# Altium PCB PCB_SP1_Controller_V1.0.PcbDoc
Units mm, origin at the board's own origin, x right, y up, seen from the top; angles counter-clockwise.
Board outline 55.14 x 44.39 mm, 2 copper layers (Top Layer, Bottom Layer); 35 components, 48 nets, 152 pads, 22 vias.
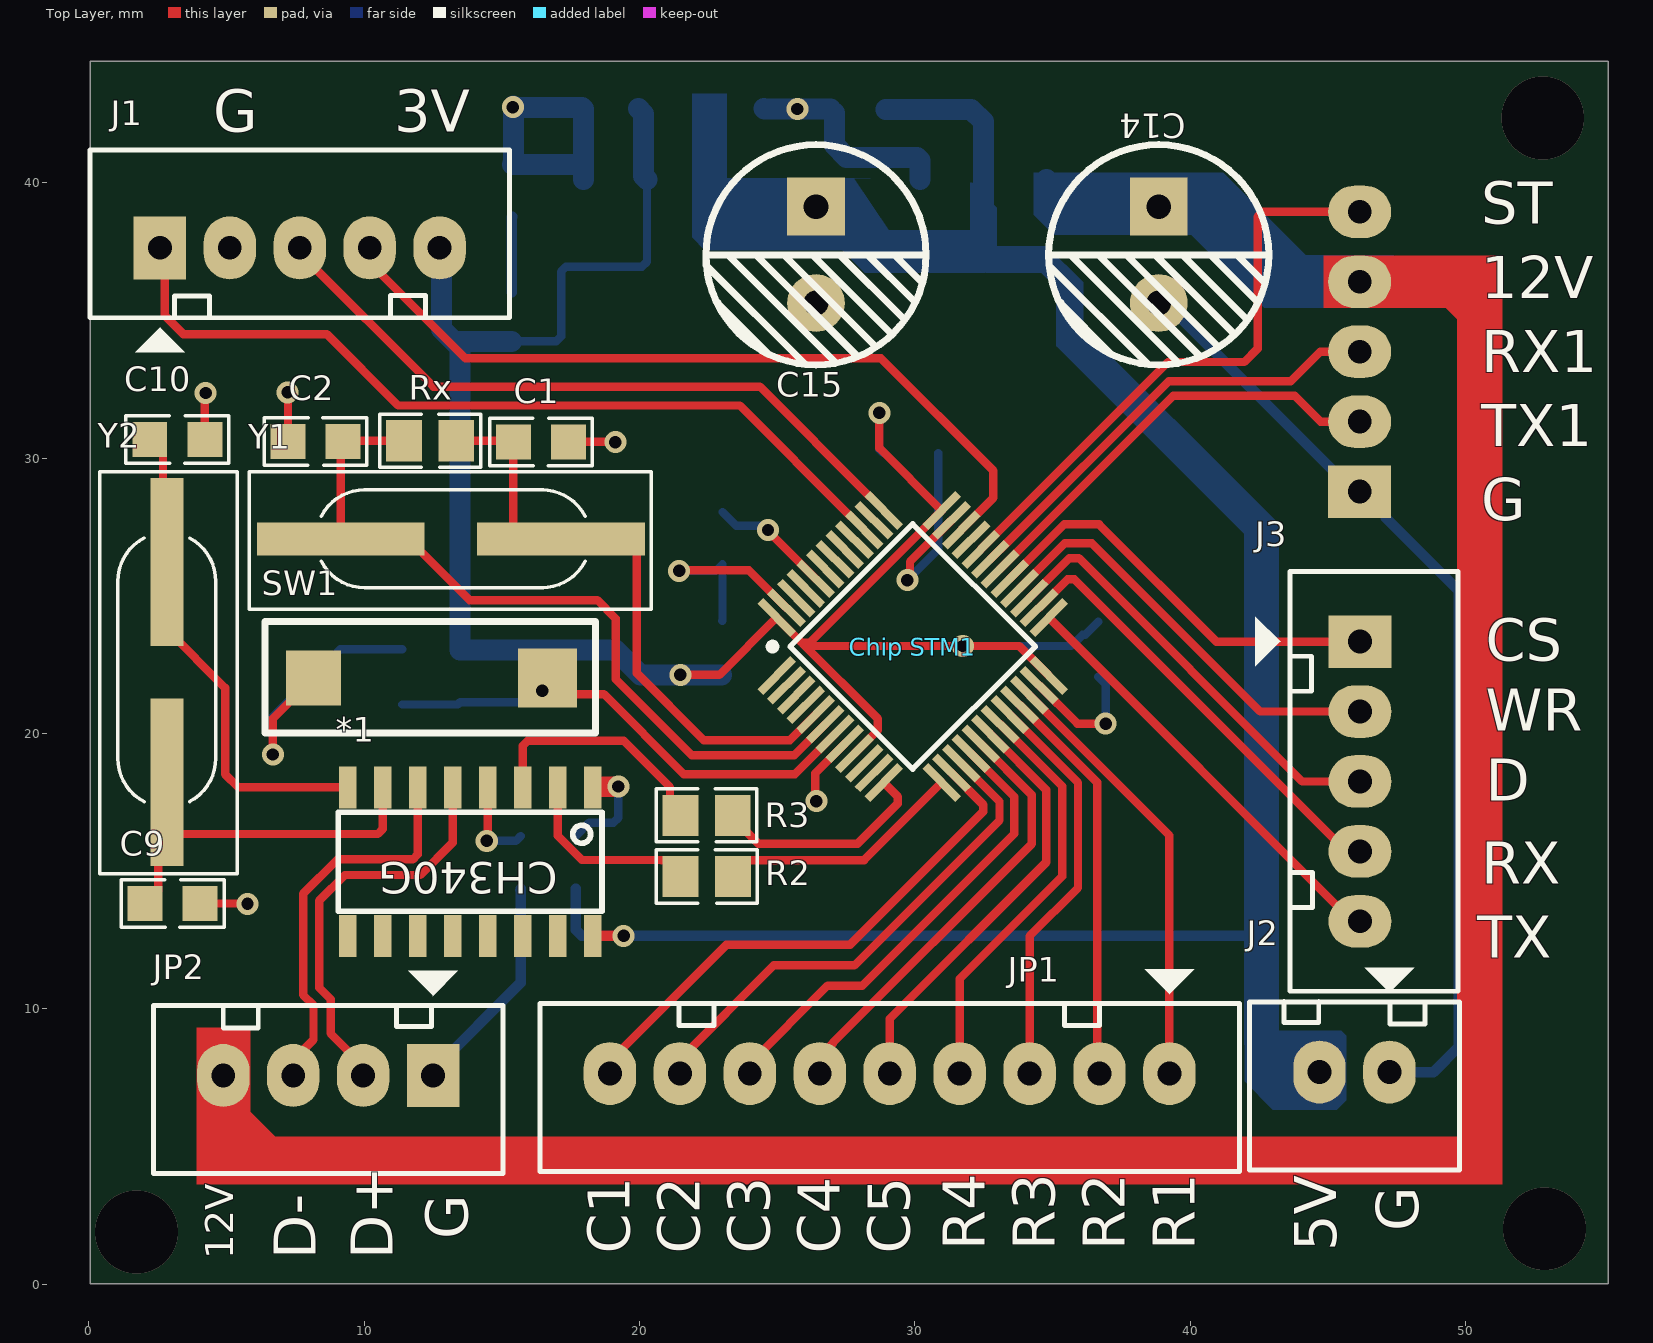
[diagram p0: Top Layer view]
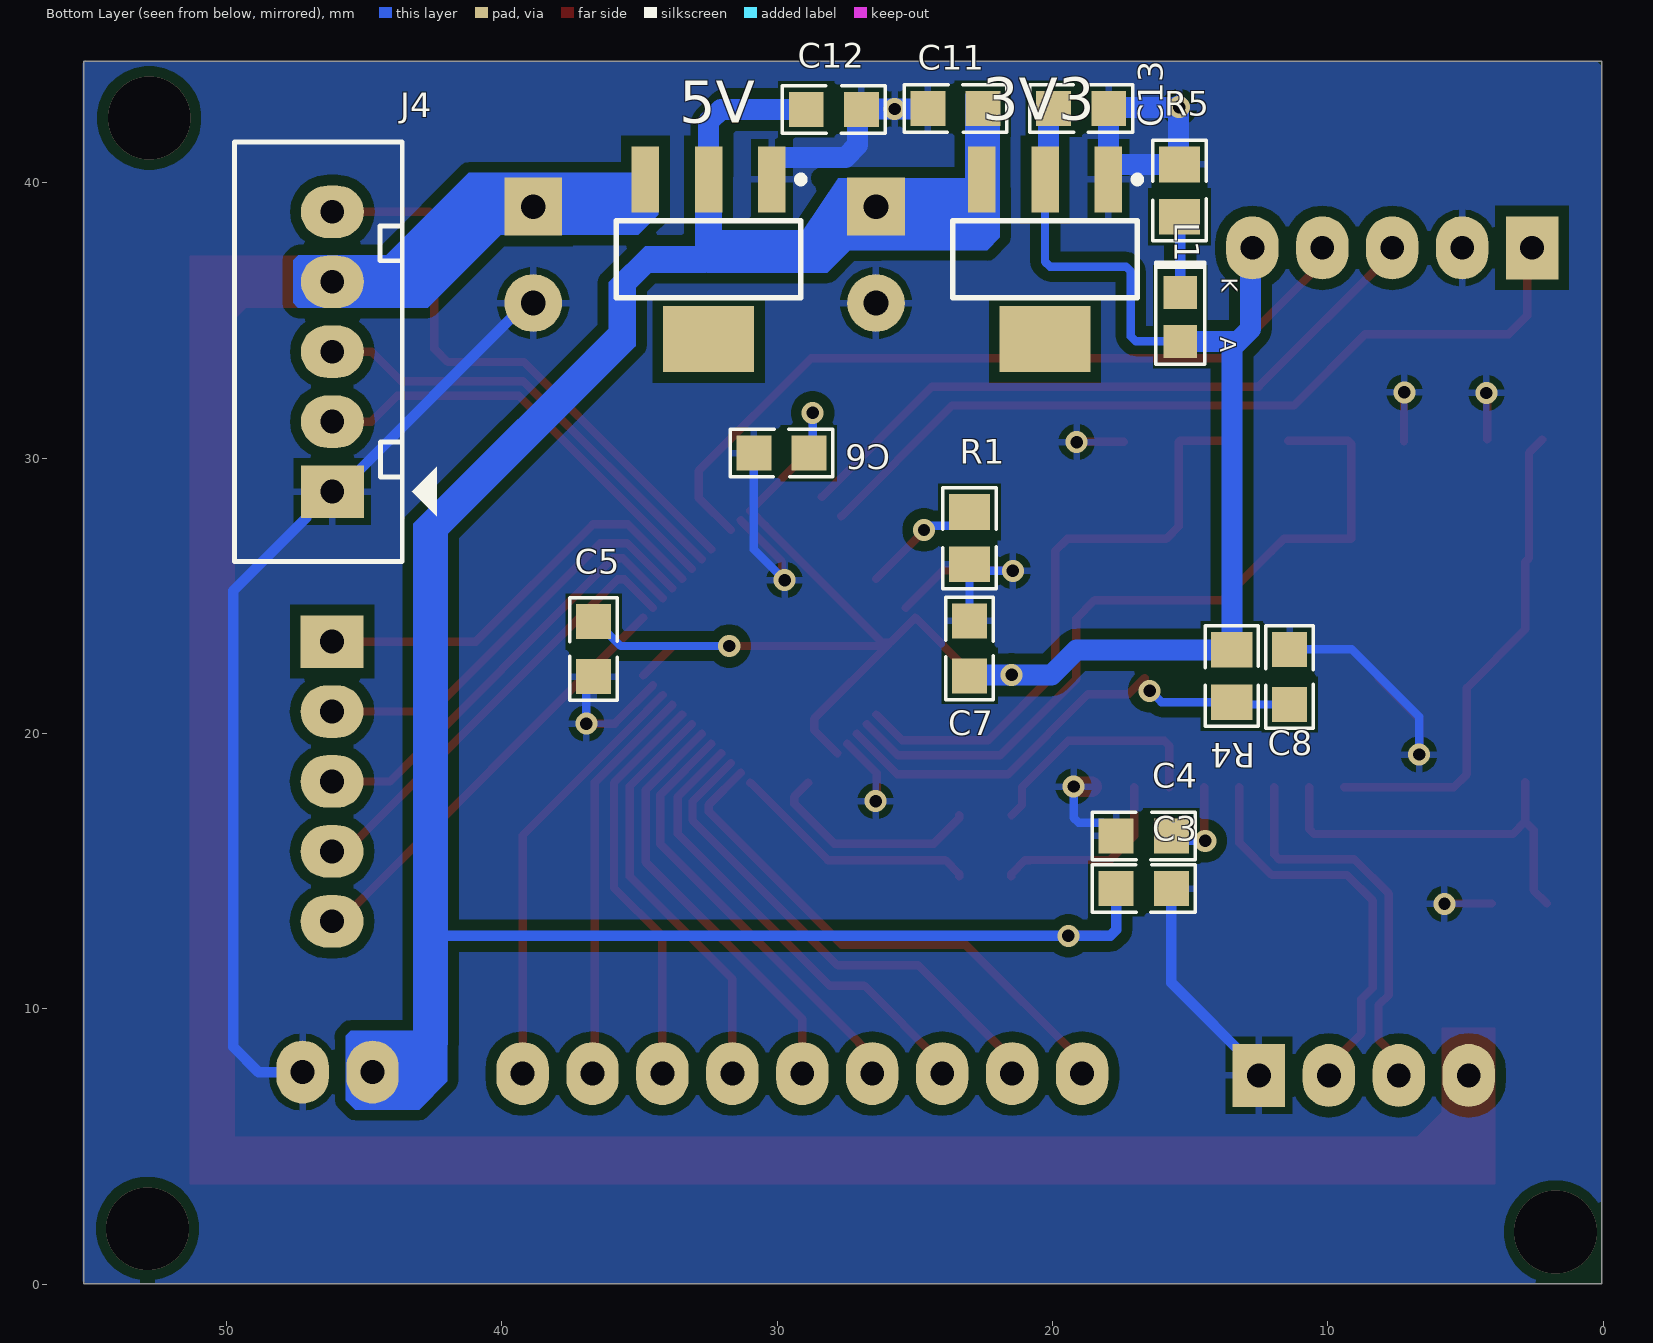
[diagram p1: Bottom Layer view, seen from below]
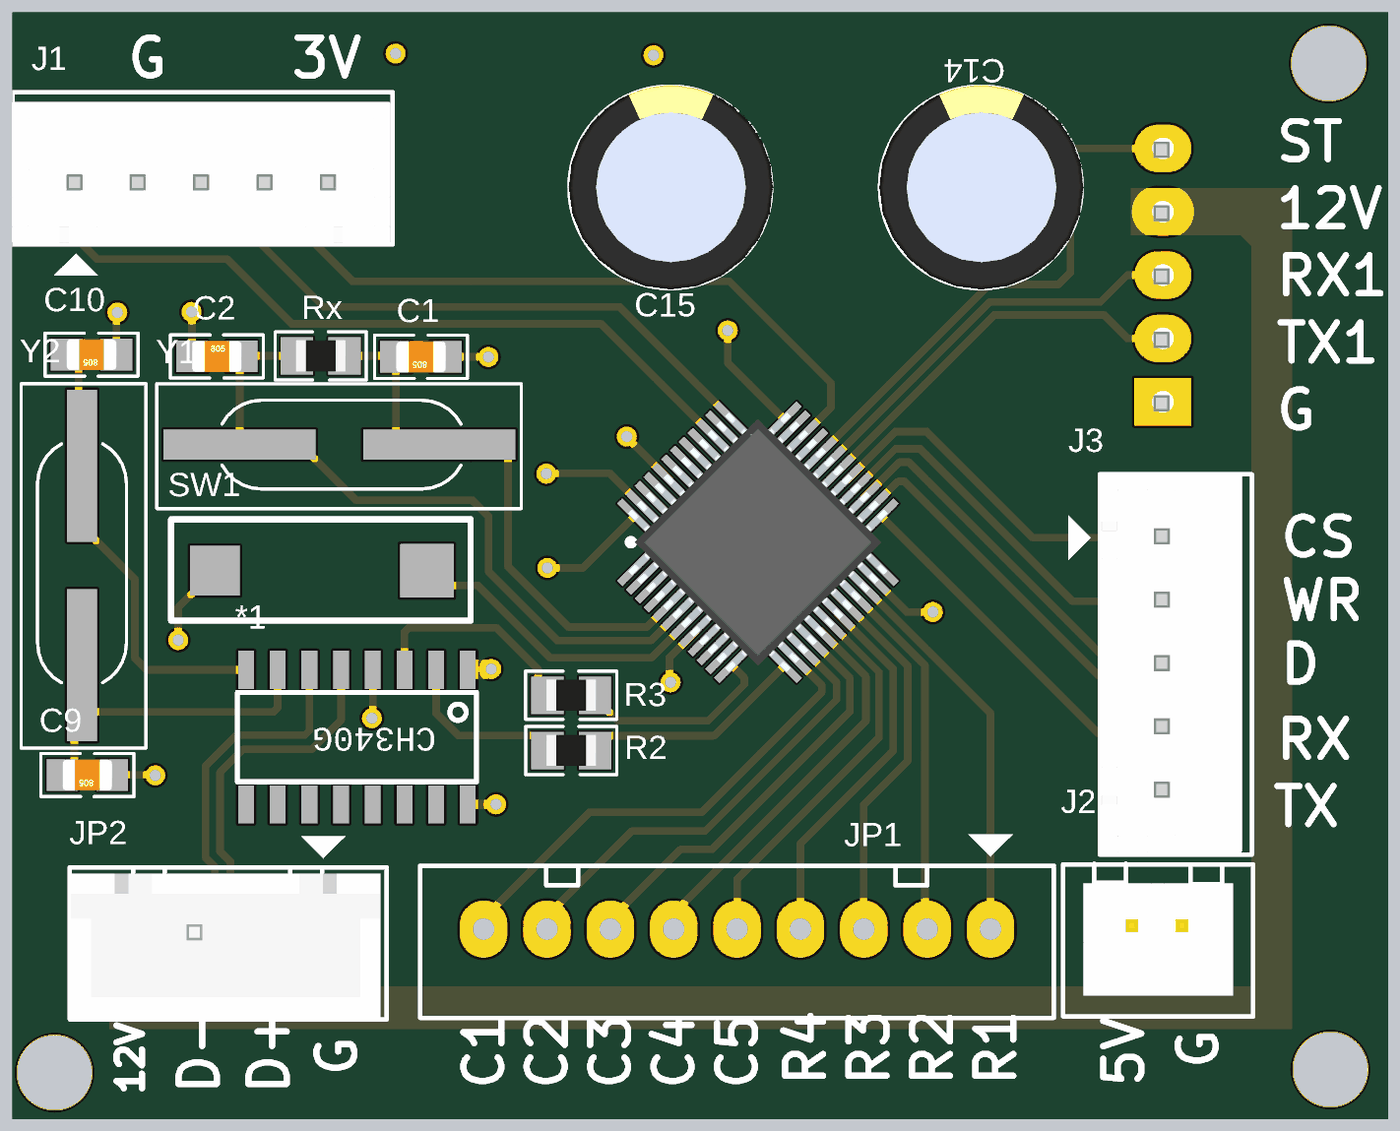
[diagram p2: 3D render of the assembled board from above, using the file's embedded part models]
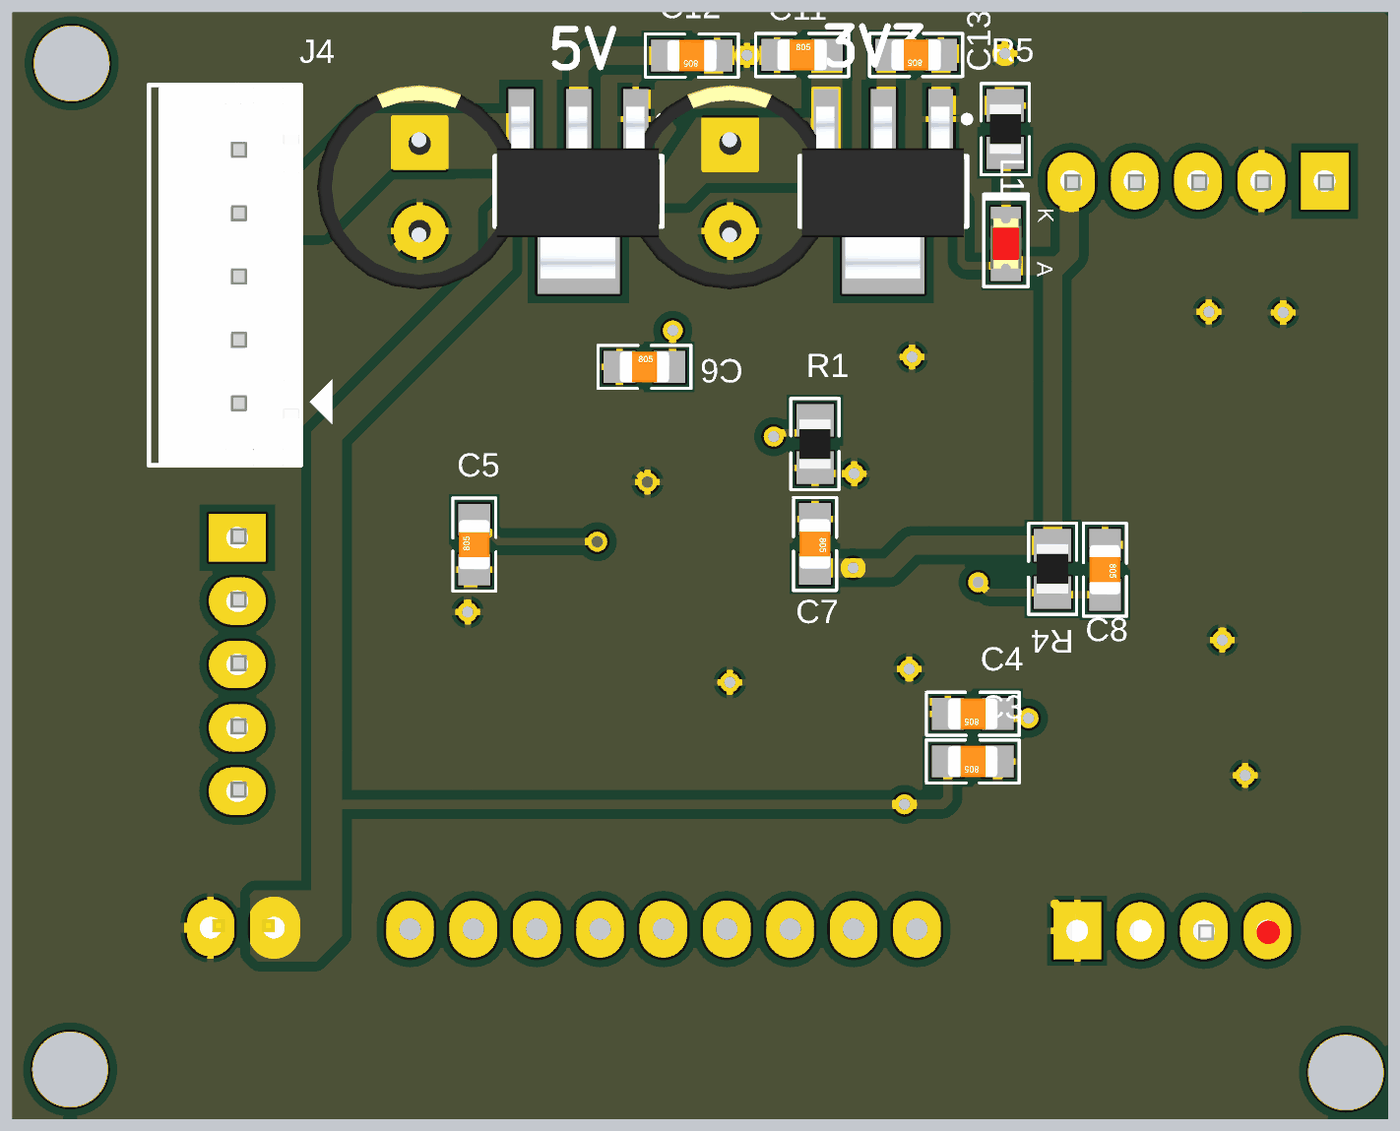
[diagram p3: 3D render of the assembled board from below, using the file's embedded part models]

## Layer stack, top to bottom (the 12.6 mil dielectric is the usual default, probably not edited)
Top Solder: solder mask 0.0102, Solder Resist, Dk 3.5
Top Layer: signal copper 0.0356
Dielectric 1: dielectric 0.32, FR-4, Dk 4.8
Bottom Layer: signal copper 0.0356
Bottom Solder: solder mask 0.0102, Solder Resist, Dk 3.5

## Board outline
0.046,0.015 55.183,0.015 55.183,44.404 0.046,44.404

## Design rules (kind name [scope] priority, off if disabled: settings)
Clearance [All] p1: gap=0.381 ignorepadtopadclearanceinfootprint=FALSE
PolygonConnect [All] p1: connectstyle=Relief reliefconductorwidth=0.254 reliefentries=4 polygonreliefangle="90 Angle" airgapwidth=0.254
RoutingVias [All] p1: holewidth=0.45 width=0.8 viastyle="Through Hole" minholewidth=0.45 minwidth=0.8 maxholewidth=0.45 maxwidth=0.8
SolderMaskExpansion [All] p1: expansion=0.102 istentingtop=FALSE
Width [All] p1: maxlimit=0.762 minlimit=0.305 preferedwidth=0.381
30 further rules are at their usual default settings.

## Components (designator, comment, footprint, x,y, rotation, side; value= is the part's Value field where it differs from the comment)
3V3 "" SOT223-4N 20.274,37.216 r270 bottom value=LM317 (schematic designator 1)
5V "LM1117" SOT223-4N 32.494,37.216 r270 bottom value=LM317
*1 "CH340G" CH340G 13.853,15.34 r270 top
C1 "22pF" CAP_0805 16.42,30.586 r180 top
C2 "22pF" CAP_0805 8.237,30.599 r0 top
C3 "0.1uF" CAP_0805 16.69,14.364 r0 bottom
C4 "0.1uF" CAP_0805 16.69,16.272 r0 bottom
C5 "0.1uF" CAP_0805 36.672,23.056 r90 bottom
C6 "0.1uF" CAP_0805 29.85,30.181 r180 bottom
C7 "0.1uF" CAP_0805 23.016,23.084 r270 bottom
C8 "0.1uF" CAP_0805 11.39,22.048 r270 bottom
C9 "22pF" CAP_0805 3.049,13.818 r180 top
C10 "22pF" CAP_0805 3.216,30.673 r180 top
C11 "0.1uF" CAP_0805 23.532,42.687 r180 bottom
C12 "0.1uF" CAP_0805 27.947,42.662 r0 bottom
C13 "0.1uF" CAP_0805 18.961,42.688 r0 bottom
C14 "4.7uF" "tu hoa 8mm" 38.862,37.379 r270 top
C15 "4.7uF" "tu hoa 8mm" 26.415,37.379 r270 top
"Chip STM1" "STM32F103C8T6" LQFP-48_19.6_393_58X11_SMD 29.927,23.152 r45 top
J1 "Debug" CON5 2.584,37.635 r0 top value="Connector 5"
J2 "5V" CON2 47.24,7.697 r180 top value="Connector 2"
J3 "LCD" CON5 46.17,23.332 r270 top value="Connector 5"
J4 "LCD" CON5 46.16,28.781 r90 bottom value="Connector 5"
JP1 "Key" CON9 39.25,7.641 r180 top value="Connector 9"
JP2 "UART2" CON4 12.505,7.575 r180 top value="Connector 4"
L1 "RED LED" LED_0805 15.363,35.123 r270 bottom (schematic designator LED1)
R1 "10Kohm" RES_0805 23.016,27.089 r90 bottom
R2 "100R" RES_0805 22.445,14.799 r180 top
R3 "100R" RES_0805 22.441,17.019 r180 top
R4 "10Kohm" RES_0805 13.49,22.083 r270 bottom
R5 "1K" RES_0805 15.389,39.715 r90 bottom
Rx "1M" RES_0805 12.401,30.622 r180 top (schematic designator Rtal1)
SW1 "\" SW_342_SMD 8.159,22.01 r180 top
Y1 "8MHz" XTAL_314_240X47_SMD 17.151,27.067 r180 top
Y2 "12MHz" XTAL_314_240X47_SMD 2.835,26.222 r270 top

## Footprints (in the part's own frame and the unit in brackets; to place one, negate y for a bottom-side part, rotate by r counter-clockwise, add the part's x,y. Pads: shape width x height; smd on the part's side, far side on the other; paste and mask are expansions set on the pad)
CAP_0805 [mm]
  rect 1.27x1.27 smd mask+0.076: 1(-1,0) 2(1,0)
  silkscreen extent -1.86,-0.86 1.86,0.86, body extent -1,-0.62 1,0.63, height 0.78
CH340G [mil]
  rect 60x25 smd: 1(-106.1,175) 2(-106.1,125) 3(-106.1,75) 4(-106.1,25) 5(-106.1,-25) 6(-106.1,-75) 7(-106.1,-125) 8(-106.1,-175) 9(106.1,-175) 10(106.1,-125) 11(106.1,-75) 12(106.1,-25) 13(106.1,25) 14(106.1,75) 15(106.1,125) 16(106.1,175)
  silkscreen extent -71,-189 71,189
CON2 [mil]
  oval 75x90 hole 34: 1(0,0) 2(100,0)
  silkscreen extent -100,-150 200,140, body extent -68,-70 168,107, height 236
CON4 [mil]
  rect 75x90 hole 34: 1(0,0)
  oval 75x90 hole 34: 2(100,0) 3(200,0) 4(300,0)
  silkscreen extent -100,-150 400,140, body extent -90,-90 398,136, height 276
CON5 [mil]
  rect 75x90 hole 34: 1(0,0)
  oval 75x90 hole 34: 2(100,0) 3(200,0) 4(300,0) 5(400,0)
  silkscreen extent -100,-150 500,140, body extent -101,-98 496,125, height 288
CON9 [mil]
  oval 75x90 hole 34: 1(0,0) 2(100,0) 3(200,0) 4(300,0) 5(400,0) 6(500,0) 7(600,0) 8(700,0) 9(800,0)
  silkscreen extent -100,-150 900,140
LED_0805 [mm]
  rect 1.2x1.2 smd mask+0.076: A(0.889,0) K(-0.889,0)
  silkscreen extent -1.99,-0.89 1.73,0.89, body extent -1.01,-0.62 1.01,0.63, height 1.1
LQFP-48_19.6_393_58X11_SMD [mm]
  rect 1.7x0.3 smd mask+0.076: 1(-4.238,2.75) 2(-4.238,2.25) 3(-4.238,1.75) 4(-4.238,1.25) 5(-4.238,0.75) 6(-4.238,0.25) 7(-4.238,-0.25) 8(-4.238,-0.75) 9(-4.238,-1.25) 10(-4.238,-1.75) 11(-4.238,-2.25) 12(-4.238,-2.75) 25(4.238,-2.75) 26(4.238,-2.25) 27(4.238,-1.75) 28(4.238,-1.25) 29(4.238,-0.75) 30(4.238,-0.25) 31(4.238,0.25) 32(4.238,0.75) 33(4.238,1.25) 34(4.238,1.75) 35(4.238,2.25) 36(4.238,2.75)
  rect 0.3x1.7 smd mask+0.076: 13(-2.75,-4.238) 14(-2.25,-4.238) 15(-1.75,-4.238) 16(-1.25,-4.238) 17(-0.75,-4.238) 18(-0.25,-4.238) 19(0.25,-4.238) 20(0.75,-4.238) 21(1.25,-4.238) 22(1.75,-4.238) 23(2.25,-4.238) 24(2.75,-4.238) 37(2.75,4.238) 38(2.25,4.238) 39(1.75,4.238) 40(1.25,4.238) 41(0.75,4.238) 42(0.25,4.238) 43(-0.25,4.238) 44(-0.75,4.238) 45(-1.25,4.238) 46(-1.75,4.238) 47(-2.25,4.238) 48(-2.75,4.238)
  silkscreen extent -3.72,-3.15 3.15,3.72, body extent -4.5,-4.5 4.5,4.5, height 1.7
RES_0805 [mm]
  rect 1.3x1.5 smd mask+0.076: 1(0.95,0) 2(-0.95,0)
  silkscreen extent -1.83,-0.97 1.83,0.97, body extent -1,-0.63 1,0.62, height 0.5
SOT223-4N [mm] "SOT223, 4-Leads, Body 6.5x3.5mm, Pitch 2.3mm, Lead Span 7mm, IPC Medium Density"
  rect 2.4x1 smd: 1(-2.9,2.3) 2(-2.9,0) 3(-2.9,-2.3)
  rect 2.4x3.3 smd: 4(2.9,0)
  silkscreen extent -3.02,-3.35 1.4,3.47, body extent -3.39,-3.27 3.5,3.23, height 1.72
SW_342_SMD [mm]
  rect 2x2 smd: 1(0,0)
  rect 2.15x2.15 smd: 2(-8.5,0)
  silkscreen extent -10.25,-2.06 1.75,2, body extent -7.17,-1.79 -1.17,1.71, height 2.4
"tu hoa 8mm" [mm]
  rect 2.1x2.1 hole 0.9: 1(-1.75,0)
  round 2.1 hole 0.9: 2(1.75,0)
  silkscreen extent -4,-4 4,4, body extent -4.1,-4.07 4.1,4.13, height 13.81
XTAL_314_240X47_SMD [mm]
  rect 6.096x1.2 smd: 1(0,0) 2(8,0)
  silkscreen extent -3.29,-2.44 11.32,2.57, body extent -2.99,-2.27 10.9,2.41, height 3.05

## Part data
3V3: library part LM1117, "3v3"
5V: "3v3"
C1 C2 C9 C10: library part CAP_22pF-50V-5%-0805, "22pF ±5% 50V Ceramic Capacitor C0G, NP0 0805 (2012 Metric)", Case/Package=0805, Manufacturer=KEMET, Manufacturer Part Number=C0805C220J5GACTU, Supplier Part Number-1=399-1113-1-ND
C3 C4 C5 C6 C7 C8 C11 C12 C13: library part CAP_0.1uF-50V-5%-0805, "0.1µF ±5% 50V Ceramic Capacitor X7R 0805 (2012 Metric)", Case/Package="0805 (2012 Metric)", Manufacturer=KEMET, Manufacturing Part Number=C0805C104J5RACTU, Supplier Part Number-1=399-1171-1-ND
C14 C15: library part "Tu Hoa 4.7uF 400V 8x12", "Cắm"
"Chip STM1": library part "IC-STM32F103C8T6 _1", "ARM® Cortex®-M3 STM32F1 Microcontroller IC 32-Bit 72MHz 64KB (64K x 8) FLASH", Case/Package=48-LQFP, Manufacturer=STMicroelectronics, Supplier Part Number-1=497-6063-ND
J1 J3 J4: library part Con5, "Connector 5"
J2: library part Con2, "Connector 2"
JP1: library part Con9, "Connector 9"
JP2: library part Con4, "Connector 4"
L1: library part LED-RED_10mA-0805, "Red 621nm LED Indication - Discrete 2V 0805 (2012 Metric)", Case/ Package=0805, Manufacturer="Lite-On Inc.", Manufacturer Part Number=LTST-C170EKT, Supplier Part Number-1=160-1178-1-ND
R1: library part RES_10K-0.125W-1%-0805, "10 kOhms ±1% 0.125W, 1/8W Chip Resistor 0805 (2012 Metric) Moisture Resistant Thick Film", Case/Package=0805, Manufacturer=Yageo, Manufacturing Part Number=RC0805FR-0710KL, Supplier Part Number-1=311-10.0KCRCT-ND
R2 R3: library part RES_0ohm-0.125W-1%-0805_1, "1000Ohms ±1% 0.125W, 1/8W Chip Resistor 0805 (2012 Metric) Moisture Resistant Thick Film", Case/Package=0805, Manufacturer=垈㎵á, Manufacturer Part Number=RC0805FR-071KL, Supplier Part Number-1=311-1.00KCRCT-ND
R4 Rx: library part RES_10MOHM-0.125W-1%-0805, "10 MOhms ±1% 0.125W, 1/8W Chip Resistor 0805 (2012 Metric) Automotive AEC-Q200, High Voltage Thick Film", Case/Package="0805 (2012 Metric)", Manufacturer="Rohm Semiconductor", Manufacturing Part Number=KTR10EZPF1005, Supplier Part Number-1=RHM10.0MAHCT-ND
R5: library part RES_1K-0.125W-1%-0805, "1 kOhms ±1% 0.125W, 1/8W Chip Resistor 0805 (2012 Metric) Moisture Resistant Thick Film", Case/Package=0805, Manufacturer=垈㎵á, Manufacturer Part Number=RC0805FR-071KL, Supplier Part Number-1=311-1.00KCRCT-ND
SW1: library part SW_KSR223GLFG-SMD, "Tactile Switch SPST-NO Top Actuated Surface Mount", Case/Package=SMD, Manufacturer=C&K, Manufacturing Part Number=KSR223GLFG, Supplier Part Number-1=401-1704-1-ND
Y1 Y2: library part XTAL_8MHZ-LFXTAL030234, "Crystals 8MHz 22pF -20C 70C", Case/Package=SMD, Manufacturer="IQD Frequency Products", Manufacturing Part Number=LFXTAL030234Reel, Supplier Part Number-1=449-LFXTAL030234REEL

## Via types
v1: diameter 0.8, hole 0.45, Top Layer to Bottom Layer, 19 vias
v2: diameter 3, hole 3, Top Layer to Bottom Layer, 3 vias

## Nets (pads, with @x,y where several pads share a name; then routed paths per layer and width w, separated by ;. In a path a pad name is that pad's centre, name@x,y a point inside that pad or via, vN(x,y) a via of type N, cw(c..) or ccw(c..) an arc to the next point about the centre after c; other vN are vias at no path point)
3V3: 3V3.2 "Chip STM1.9" "Chip STM1.24" "Chip STM1.36" "Chip STM1.48" C5.2 C6.2 C7.2 C13.2 J1.5 L1.A R4.2 | length 78.8
  Top Layer w0.305: v1(21.487,22.123) 22.904,22.123 24.986,24.204 25.892,23.297 26.191,23.297 ; 25.924,23.266 28.661,20.529 28.661,20.118 27.814,19.271 ; v1(28.715,31.641) 28.715,30.357 30.979,28.093 30.979,28.09 30.422,27.533 30.422,27.528 26.191,23.297 ; 34.868,22.1 33.796,23.172 v1(31.744,23.172) 26.317,23.172 26.191,23.297
  Bottom Layer w0.305: L1.A 16.976,34.234 17.155,34.413 17.155,36.772 17.333,36.95 20.095,36.95 20.274,37.129 3V3.2 ; C7.2@22.977,22.123 C7.2 ; v1(28.715,31.641) 28.715,30.316 C6.2 ; v1(31.744,23.172) 35.69,23.172 36.092,23.574 36.189,23.574 C5.2
  Bottom Layer w0.762: J1.5 12.812,37.567 12.812,34.68 13.258,34.234 ; L1.A 13.258,34.234 ; C13.2 20.155,42.493 20.155,40.235 3V3.2 ; C7.2@22.977,22.123 20.034,22.123 19.124,23.033 R4.2 13.49,34.003 13.258,34.234
5V: 3V3.3 5V.2 *1.16 C3.2 C11.2 C12.2 C15.1 J2.2 | length 50
  Top Layer w0.381: *1.16 19.427,12.645 v1(19.429,12.643)
  Bottom Layer w0.381: C3.2 17.69,12.867 17.913,12.643 v1(19.429,12.643) 42.203,12.643 42.28,12.721 42.492,12.721
  Bottom Layer w0.762: C11.2 22.553,42.667 22.553,40.137 3V3.3 22.574,39.416 22.743,39.247 26.296,39.247 27.084,38.46 27.771,38.46 28.916,37.315 32.048,37.315 32.494,37.762 32.494,42.215 32.048,42.662 C12.2
12V: 5V.3 C14.1 J4.4 JP2.4 | length 13.4
  Bottom Layer w0.762: 5V.3 34.794,39.425 34.913,39.306 38.685,39.306 C14.1 ; C14.1@38.862,38.977 39.761,38.977 39.913,39.129 40.963,39.129 43.691,36.401 J4.4
COL1: "Chip STM1.14" JP1.9 | length 19.7
  Top Layer w0.305: JP1.9 18.93,8.096 23.156,12.322 27.656,12.322 32.489,17.155 32.489,17.408 31.333,18.564
COL2: "Chip STM1.15" JP1.8 | length 18.4
  Top Layer w0.305: JP1.8 21.47,8.164 24.878,11.571 27.809,11.571 33.079,16.841 33.079,17.525 31.686,18.918
COL3: "Chip STM1.16" JP1.7 | length 17
  Top Layer w0.305: JP1.7 24.01,8.011 26.838,10.839 28.099,10.839 33.618,16.357 33.618,17.691 32.04,19.269 32.04,19.271
COL4: "Chip STM1.17" JP1.6 | length 15.9
  Top Layer w0.305: JP1.6 26.55,8.265 27.016,8.73 27.016,8.75 34.251,15.985 34.251,17.767 32.393,19.625
CS: "Chip STM1.29" J3.1 | length 15.3
  Top Layer w0.305: 33.454,25.618 34.535,26.7 35.425,27.589 36.695,27.589 40.952,23.332 J3.1
DATA: "Chip STM1.27" J3.3 | length 16
  Top Layer w0.305: 34.161,24.911 35.614,26.364 35.96,26.364 44.072,18.252 J3.3
debug: "Chip STM1.39" J1.1 | length 30.5
  Top Layer w0.305: J1.1 2.76,37.459 2.76,35.169 3.432,34.497 8.643,34.497 11.235,31.906 23.648,31.906 27.674,27.879
GND: 3V3.1 5V.1 "Chip STM1.8" "Chip STM1.23" "Chip STM1.35" "Chip STM1.47" *1.1 C1.1 C2.1 C3.1 C4.2 C5.1 C6.1 C7.1 C8.1 C9.1 C10.1 C11.1 C12.1 C13.1 C14.2 C15.2 J1.2 J2.1 J4.1 JP2.1 R1.2 R5.1 SW1.1 | length 105.1
  Top Layer w0.305: C9.1 5.755,13.818 v1(5.768,13.806) ; C10.1 4.216,32.331 v1(4.248,32.362) ; v1(6.689,19.23) 6.689,20.54 7.311,21.162 SW1.1 ; v1(7.225,32.386) 7.237,32.374 C2.1 ; C1.1 19.117,30.586 v1(19.124,30.578) ; v1(21.446,25.902) 21.462,25.918 23.979,25.918 25.339,24.558 ; v1(26.427,17.536) 26.381,17.581 26.381,18.545 27.461,19.625 ; v1(29.734,25.562) 29.829,25.657 29.829,26.236 31.333,27.74 ; 34.515,21.746 35.907,20.354 v1(36.936,20.354)
  Top Layer w0.762: *1.1@18.581,18.06 19.231,18.06 v1(19.238,18.068)
  Bottom Layer w0.305: v1(6.689,19.23) 6.689,20.606 9.131,23.048 C8.1 ; C3.1@15.629,14.303 C3.1 ; C4.2 18.172,16.755 19.06,16.755 19.238,16.933 v1(19.238,18.068) ; v1(21.446,25.902) 22.779,25.902 R1.2 C7.1 ; v1(29.734,25.562) 30.85,26.678 C6.1 ; C5.1 36.936,21.792 v1(36.936,20.354)
  Bottom Layer w0.381: JP2.1 12.505,7.765 15.69,10.949 C3.1 ; C14.2 39.122,35.629 45.97,28.781 J4.1 46.351,28.781 47.113,28.019 47.113,27.829 49.763,25.178 49.763,8.62 48.84,7.697 J2.1
  Bottom Layer w0.762: R5.1 R5.1@15.421,40.666 ; v1(15.404,42.745) 15.411,42.737 v1@15.421,42.737 ; v1@15.421,42.782 v1@15.421,42.737 ; 3V3.1@17.919,40.666 R5.1@15.421,40.666 ; 3V3.1@17.967,40.123 17.967,42.681 C13.1 17.911,42.737 v1@15.421,42.737 ; C11.1 24.545,42.675 v1(25.74,42.675) 26.935,42.675 C12.1 27.08,42.53 27.08,41.365 27.526,40.919 30.075,40.919 30.194,40.8 5V.1 ; R5.1@15.421,40.666 v1@15.421,42.737
MP3_RX: "Chip STM1.26" J3.4 | length 16.2
  Top Layer w0.305: 34.515,24.558 34.518,24.558 35.55,25.59 35.803,25.59 45.68,15.712 J3.4
MP3_TX: "Chip STM1.25" J3.5 | length 15.9
  Top Layer w0.305: 34.868,24.204 45.9,13.172 J3.5
Net*1_2: *1.2 R2.1 | length 6.9
  Top Layer w0.305: *1.2 17.028,16.283 17.913,15.398 20.819,15.398 20.821,15.396 20.997,15.396 21.495,14.898 R2.1
Net*1_3: *1.3 R3.1 | length 8.8
  Top Layer w0.305: *1.3 15.758,19.546 15.936,19.724 19.436,19.724 21.112,18.048 21.112,17.398 R3.1
Net*1_4: *1.4 C4.1 | length 3.3
  Top Layer w0.305: v1(14.455,16.097) 14.488,16.13 *1.4
  Bottom Layer w0.305: v1(14.455,16.097) 15.515,16.097 C4.1
Net*1_5: *1.5 JP2.2 | length 14.7
  Top Layer w0.305: JP2.2 9.965,7.924 8.784,9.105 8.784,10.345 8.367,10.762 8.367,13.919 9.302,14.854 12.045,14.854 13.218,16.027 *1.5
Net*1_6: *1.6 JP2.3 | length 14.2
  Top Layer w0.305: JP2.3 7.425,8.135 8.162,8.872 8.162,10.128 7.789,10.501 7.789,14.173 9.037,15.421 11.769,15.421 11.948,15.6 *1.6
Net*1_7: *1.7 C9.2 Y2.2 | length 14.3
  Top Layer w0.305: C9.2 2.526,14.295 2.526,16.484 Y2.2@2.835,16.793 ; Y2.2 Y2.2@2.835,16.793 ; *1.7 10.678,16.524 10.499,16.345 3.283,16.345 Y2.2@2.835,16.793
Net*1_8: *1.8 C10.2 Y2.1 | length 17.9
  Top Layer w0.305: C10.2 2.698,30.19 2.698,26.358 Y2.1 2.835,23.774 4.955,21.654 4.955,18.514 5.433,18.035 *1.8
"NetChip STM1_44": "Chip STM1.44" R1.1 | length 4.4
  Top Layer w0.305: v1(24.669,27.387) 24.669,27.352 26.4,25.622 26.4,25.618
  Bottom Layer w0.305: R1.1 23.514,27.542 24.515,27.542 v1(24.669,27.387)
NetLED1_K: L1.K R5.2 | length 2.8
  Bottom Layer w0.381: L1.K 15.363,38.739 R5.2
NRST: "Chip STM1.7" C8.2 R4.1 SW1.2 | length 18.3
  Top Layer w0.305: v1(16.477,21.546) 16.659,21.728 SW1.2 17.247,21.422 18.708,21.422 21.609,18.521 25.65,18.521 27.107,19.978
  Bottom Layer w0.305: C8.2 13.405,21.048 R4.1 16.05,21.133 16.464,21.546 v1(16.477,21.546)
PA0: "Chip STM1.10"
PA1: "Chip STM1.11"
PA15: "Chip STM1.38"
PB4: "Chip STM1.40"
PB5: "Chip STM1.41"
PB6: "Chip STM1.42"
PB7: "Chip STM1.43"
PB8: "Chip STM1.45"
PB9: "Chip STM1.46"
PC13: "Chip STM1.2"
ROW1: "Chip STM1.22" JP1.1 | length 15.9
  Top Layer w0.305: 34.161,21.393 34.653,20.901 34.653,20.898 34.718,20.832 34.718,20.824 39.25,16.291 JP1.1
ROW2: "Chip STM1.21" JP1.2 | length 14.6
  Top Layer w0.305: 33.808,21.039 36.622,18.225 36.622,7.73 JP1.2
ROW3: "Chip STM1.20" JP1.3 | length 14.8
  Top Layer w0.305: 33.454,20.685 35.928,18.211 35.928,14.39 34.17,12.632 JP1.3
ROW4: "Chip STM1.19" JP1.4 | length 15.2
  Top Layer w0.305: JP1.4 31.63,11.081 35.352,14.802 35.352,18.08 33.1,20.332
ROW5: "Chip STM1.18" JP1.5 | length 15.5
  Top Layer w0.305: JP1.5 29.09,9.631 34.776,15.317 34.776,17.949 32.747,19.978
RX1: "Chip STM1.31" J4.3 | length 16.5
  Top Layer w0.305: 32.747,26.325 33.113,26.691 33.116,26.691 33.122,26.685 39.22,32.783 43.654,32.783 44.732,33.861 J4.3
RX2: "Chip STM1.13" R2.2 | length 9.1
  Top Layer w0.305: R2.2 23.395,14.898 23.892,15.395 28.164,15.395 30.979,18.211
stuff: "Chip STM1.32" J4.5 | length 21.7
  Top Layer w0.305: 32.393,26.679 32.393,26.682 39.198,33.487 41.975,33.487 42.456,33.968 42.456,38.763 42.635,38.941 J4.5
SWCLK: "Chip STM1.37" J1.3 | length 24.6
  Top Layer w0.305: J1.3 7.664,37.444 12.517,32.592 24.376,32.592 28.381,28.586
SWDIO: "Chip STM1.34" J1.4 | length 29
  Top Layer w0.305: J1.4 10.204,37.096 13.683,33.617 28.776,33.617 32.85,29.543 32.85,28.55 31.686,27.386
TX1: "Chip STM1.30" J4.2 | length 16.1
  Top Layer w0.305: 33.1,25.972 39.393,32.265 43.798,32.265 44.739,31.324 46.158,31.324 J4.2
TX2: "Chip STM1.12" R3.2 | length 8.1
  Top Layer w0.305: R3.2 23.391,16.919 24.321,15.989 27.925,15.989 29.384,17.449 29.384,17.701 28.875,18.211
WR: "Chip STM1.28" J3.2 | length 15.6
  Top Layer w0.305: 33.808,25.265 35.442,26.899 36.437,26.899 42.544,20.792 J3.2
XTALA: "Chip STM1.5" C1.2 Rx.2 Y1.1 | length 22.3
  Top Layer w0.305: Rx.2 15.384,30.622 C1.2 15.42,27.514 15.868,27.067 19.461,27.067 19.908,26.619 19.908,22.183 22.335,19.756 25.471,19.756 26.4,20.685
XTALB: "Chip STM1.6" C2.2 Rx.1 Y1.2 | length 28.4
  Top Layer w0.305: Rx.1 9.26,30.622 C2.2 9.151,30.514 Y1.2 11.599,27.067 12.047,26.619 13.83,24.836 18.471,24.836 19.135,24.172 19.135,21.971 21.898,19.208 25.63,19.208 26.753,20.332
pads on no net: 3V3.4 5V.4 "Chip STM1.1" "Chip STM1.3" "Chip STM1.4" "Chip STM1.33" *1.9 *1.10 *1.11 *1.12 *1.13 *1.14 *1.15
copper on no net:
  other v2: 1.734,1.888 52.873,2.013 52.811,42.349

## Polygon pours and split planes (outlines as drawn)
GND on Bottom Layer "GND_L02_P000" (solid, pour order 0): 0.213,44.386 0.052,44.225 0.052,0.022 55.199,0.022 55.247,0.07 55.22,0.097 55.22,44.424

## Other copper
Top Layer:
  region net 12V: 5.859,9.025 5.859,6.257 6.769,5.347 49.698,5.347 49.698,35.038 49.286,35.45 44.862,35.45 44.862,37.348 51.346,37.348 51.346,3.624 3.924,3.624 3.924,9.3 4.088,9.299 5.859,9.299
Bottom Layer:
  region net 5V: 45.669,8.923 45.669,6.674 45.325,6.33 43.012,6.33 41.978,7.363 41.978,9.198 45.499,9.198 45.675,9.022 45.675,8.894
  region net 5V: 32.535,37.692 34.798,37.697 36.129,36.39 36.129,33.933 35.134,34.067 35.134,36.191 34.591,36.734 32.595,36.734
  region net 5V: 35.59,35.227 43.212,27.604 43.212,8.69 41.963,8.69 41.963,27.249 35.131,34.081
  region net 5V: 21.922,43.238 21.916,38.012 22.381,37.546 26.214,37.546 27.359,37.551 28.176,36.734 32.559,36.734 32.985,37.16 32.985,39.093 32.087,39.99 32.022,39.99 32.022,38.167 32.027,38.268 29.058,38.268 27.78,40.167 28.384,40.167 23.172,40.167 23.172,43.237
  region net 12V: 34.323,40.357 34.323,38.836 35.045,38.115 40.041,38.115 42.693,35.463 47.408,35.463 47.576,35.63 47.576,37.174 47.391,37.359 44.195,37.359 41.197,40.357

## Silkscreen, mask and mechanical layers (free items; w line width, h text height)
Top Overlay:
  text "G" at 4.526,41.849 h1.52
  text "3V" at 11.094,41.849 h1.52
  text "ST" at 50.571,38.499 h1.52
  text "12V" at 50.571,35.81 h1.52
  text "RX1" at 50.571,33.12 h1.52
  text "TX1" at 50.571,30.43 h1.52
  text "G" at 50.571,27.741 h1.52
  text "CS" at 50.742,22.641 h1.52
  text "WR" at 50.742,20.097 h1.52
  text "D" at 50.742,17.554 h1.52
  text "RX" at 50.571,14.532 h1.52
  text "TX" at 50.439,11.842 h1.52
  text "G" at 48.291,1.914 h1.52 r90
  text "G" at 13.767,1.624 h1.52 r90
  text "R4" at 32.551,1.233 h1.52 r90
  text "R3" at 35.093,1.233 h1.52 r90
  text "R2" at 37.634,1.233 h1.52 r90
  text "R1" at 40.176,1.233 h1.52 r90
  text "5V" at 45.303,1.185 h1.52 r90
  text "C1" at 19.653,1.093 h1.52 r90
  text "C2" at 22.194,1.093 h1.52 r90
  text "C3" at 24.736,1.093 h1.52 r90
  text "C4" at 27.277,1.093 h1.52 r90
  text "C5" at 29.819,1.093 h1.52 r90
  text "12V" at 5.248,0.902 h1.02 r90
  text "D-" at 8.244,0.902 h1.52 r90
  text "D+" at 11.046,0.902 h1.52 r90
  text "G" at 18.139,-61.659 h1.52 r90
